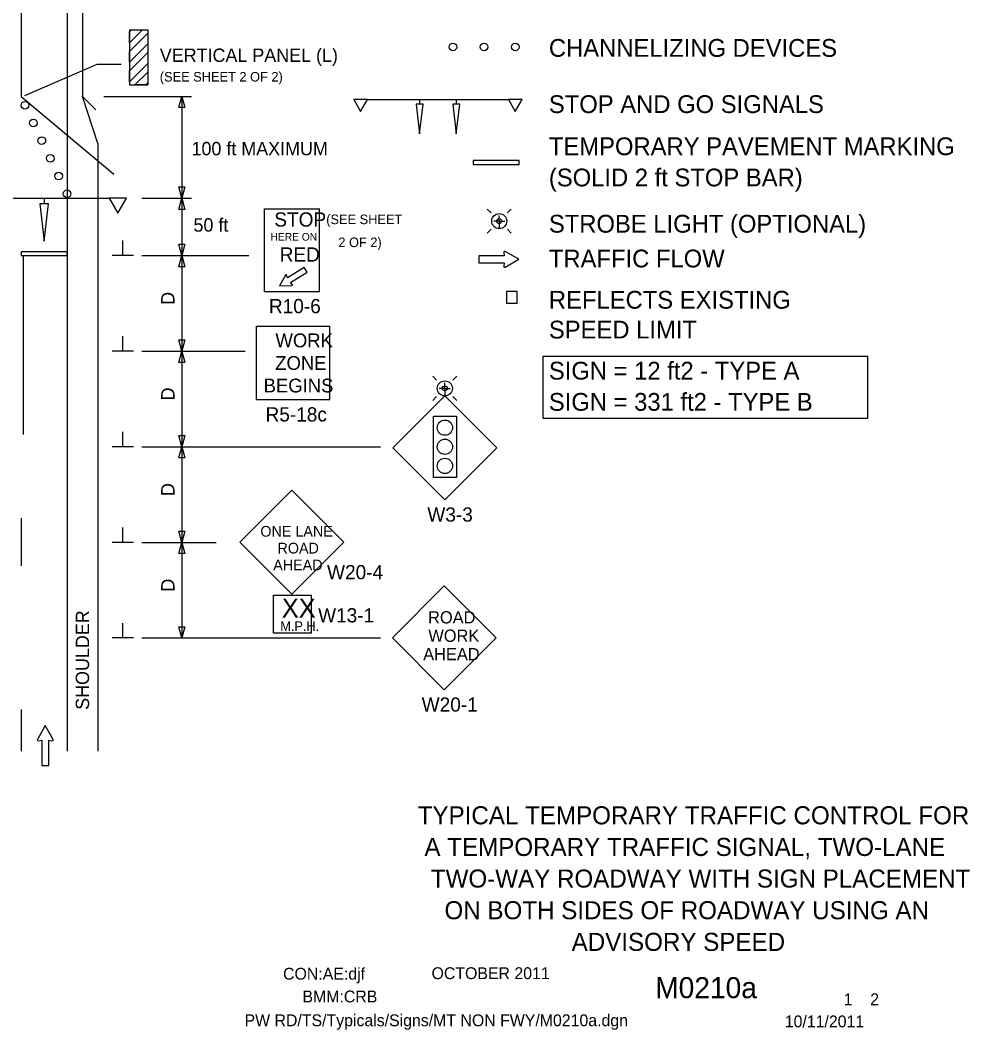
# Model space of a CAD drawing. Extents: x 16520 to 18479, y 5662 to 6927.
# Drawn here: x 16953 to 17450, y 5932 to 6460 of the extents above; entities that cross this region are included whole.
import ezdxf

# ---------------------------------------------------------------- set-up
doc = ezdxf.new("R2010")
doc.units = 0
for name, color, linetype in [('ALI_LEGAL_EX', 7, 'Continuous'), ('BORDER', 7, 'Continuous'), ('BORDER_SIGNAL_WO', 7, 'Continuous'), ('MT_SCRATCH_LEVEL_E', 7, 'Continuous'), ('PAVT_EDGE_EX', 7, 'Continuous'), ('TRAFFIC_SIGNS_PR', 7, 'Continuous'), ('TYPICAL_TEXT_DIMEN_EX', 7, 'Continuous'), ('TYPICAL_TEXT_DIMEN_PR', 7, 'Continuous')]:
    doc.layers.add(name, color=color, linetype=linetype)

msp = doc.modelspace()

# ---------------------------------------------------------------- linework, layer by layer
at = {"layer": 'ALI_LEGAL_EX'}
for points in [[(16954.78, 6336.76), (16954.78, 6243.13)], [(16953.78, 6199.43), (16953.78, 6174.43)], [(16953.78, 6099.43), (16953.78, 6077.5)]]:
    msp.add_lwpolyline(points, dxfattribs=at)
at = {"layer": 'MT_SCRATCH_LEVEL_E'}
for p, q in [((17206.32, 6336.64), (17193.07, 6336.64)), ((17193.07, 6336.64), (17193.07, 6332.9)), ((17206.32, 6336.64), (17193.07, 6336.64)), ((17193.07, 6336.64), (17193.07, 6332.9)), ((17206.01, 6338.42), (17206.32, 6336.64)), ((17206.01, 6338.42), (17206.32, 6336.64)), ((17213.93, 6334.79), (17206.69, 6338.9)), ((17213.93, 6334.79), (17206.69, 6338.9)), ((17193.07, 6332.9), (17206.32, 6332.9)), ((17193.07, 6332.9), (17206.32, 6332.9)), ((17206.32, 6332.9), (17206.01, 6331.12)), ((17206.32, 6332.9), (17206.01, 6331.12)), ((17206.69, 6330.64), (17213.93, 6334.79)), ((17206.69, 6330.64), (17213.93, 6334.79)), ((16966.37, 6090.97), (16962.26, 6083.73)), ((16966.37, 6090.97), (16962.26, 6083.73)), ((16970.52, 6083.73), (16966.37, 6090.97)), ((16970.52, 6083.73), (16966.37, 6090.97)), ((16962.74, 6083.04), (16964.52, 6083.36)), ((16962.74, 6083.04), (16964.52, 6083.36)), ((16964.52, 6083.36), (16964.52, 6070.1)), ((16964.52, 6083.36), (16964.52, 6070.1)), ((16968.26, 6070.1), (16968.26, 6083.36)), ((16968.26, 6083.36), (16970.04, 6083.04)), ((16968.26, 6070.1), (16968.26, 6083.36)), ((16968.26, 6083.36), (16970.04, 6083.04)), ((16964.52, 6070.1), (16968.26, 6070.1)), ((16964.52, 6070.1), (16968.26, 6070.1))]:
    msp.add_line(p, q, dxfattribs=at)
for centre, start, end in [((17206.47, 6338.49), 60.4248, 189.9638), ((17206.47, 6338.49), 60.4248, 189.9638), ((17206.47, 6331.05), 170.0362, 299.7731), ((17206.47, 6331.05), 170.0362, 299.7731), ((16962.67, 6083.5), 150.4248, 279.9638), ((16962.67, 6083.5), 150.4248, 279.9638), ((16970.11, 6083.5), 260.0362, 29.7731), ((16970.11, 6083.5), 260.0362, 29.7731)]:
    msp.add_arc(centre, 0.463, start, end, dxfattribs=at)
at = {"layer": 'PAVT_EDGE_EX'}
for p, q in [((16977.78, 6899.43), (16977.78, 6077.5)), ((16953.78, 6551.35), (16953.78, 6419.96)), ((16985.78, 6551.35), (16985.78, 6419.96)), ((16953.78, 6419.96), (17002.19, 6379.34)), ((16985.78, 6419.96), (16992.85, 6412.89)), ((16993.78, 6395.26), (16985.78, 6419.96)), ((16993.78, 6395.26), (16993.78, 6077.5))]:
    msp.add_line(p, q, dxfattribs=at)
at = {"layer": 'TRAFFIC_SIGNS_PR'}
for p, q in [((17010.4, 6454.77), (17020, 6454.77)), ((17010.4, 6454.77), (17010.4, 6425.97)), ((17010.4, 6453.68), (17011.49, 6454.77)), ((17010.4, 6448.02), (17017.15, 6454.77)), ((17010.4, 6454.77), (17020, 6454.77)), ((17010.4, 6454.77), (17010.4, 6425.97)), ((17010.4, 6453.68), (17011.49, 6454.77)), ((17010.4, 6448.02), (17017.15, 6454.77)), ((17010.4, 6443.5), (17020, 6453.1)), ((17010.4, 6443.5), (17020, 6453.1)), ((17020, 6454.77), (17020, 6425.97)), ((17020, 6454.77), (17020, 6425.97)), ((17010.4, 6437.84), (17020, 6447.44)), ((17010.4, 6437.84), (17020, 6447.44)), ((17010.4, 6433.32), (17020, 6442.92)), ((17010.4, 6433.32), (17020, 6442.92)), ((17011.81, 6444.91), (17013.23, 6446.33)), ((17011.81, 6444.91), (17013.23, 6446.33)), ((17010.4, 6427.66), (17020, 6437.26)), ((17010.4, 6427.66), (17020, 6437.26)), ((17013.24, 6425.97), (17020, 6432.73)), ((17013.24, 6425.97), (17020, 6432.73)), ((17010.4, 6425.97), (17020, 6425.97)), ((17010.4, 6425.97), (17020, 6425.97)), ((17018.89, 6425.97), (17020, 6427.08)), ((17018.89, 6425.97), (17020, 6427.08)), ((17134.84, 6418.4), (17208.44, 6418.4)), ((17162.04, 6418.4), (17162.04, 6415.98)), ((17181.24, 6418.4), (17181.24, 6415.98)), ((16907.78, 6366.76), (16999.78, 6366.76)), ((16965.78, 6366.76), (16965.78, 6363.74)), ((17080.91, 6361.23), (17109.71, 6361.23)), ((17080.91, 6318.03), (17080.91, 6361.23)), ((17095.31, 6361.23), (17095.31, 6361.23)), ((17109.71, 6318.03), (17109.71, 6361.23)), ((17199.4, 6359.04), (17197.37, 6361.07)), ((17203.68, 6354.76), (17203.68, 6357.63)), ((17207.96, 6359.04), (17209.99, 6361.07)), ((17203.68, 6354.76), (17200.8, 6354.76)), ((17203.68, 6354.76), (17203.68, 6350.82)), ((17203.68, 6354.76), (17206.56, 6354.76)), ((17199.4, 6350.47), (17197.37, 6348.44)), ((17209.99, 6348.44), (17207.96, 6350.47)), ((17080.91, 6318.03), (17109.71, 6318.03)), ((17076.71, 6261.4), (17076.71, 6299.8)), ((17076.71, 6299.8), (17115.11, 6299.8)), ((17115.11, 6261.4), (17115.11, 6299.8)), ((17170.94, 6271.56), (17168.91, 6273.59)), ((17179.5, 6271.56), (17181.53, 6273.59)), ((17175.22, 6267.28), (17172.34, 6267.28)), ((17175.22, 6267.28), (17175.22, 6270.16)), ((17175.22, 6267.28), (17175.22, 6263.34)), ((17175.22, 6267.28), (17178.1, 6267.28)), ((17175.22, 6263.34), (17148.07, 6236.19)), ((17170.94, 6263), (17168.91, 6260.96)), ((17202.37, 6236.19), (17175.22, 6263.34)), ((17181.53, 6260.96), (17179.5, 6263)), ((17076.71, 6261.4), (17115.11, 6261.4)), ((17148.07, 6236.19), (17175.22, 6209.03)), ((17175.22, 6209.03), (17202.37, 6236.19)), ((17095.23, 6214.01), (17068.08, 6186.86)), ((17122.39, 6186.86), (17095.23, 6214.01)), ((17068.08, 6186.86), (17095.23, 6159.71)), ((17095.23, 6159.71), (17122.39, 6186.86)), ((17174.97, 6163.96), (17147.82, 6136.81)), ((17202.12, 6136.81), (17174.97, 6163.96)), ((17085.63, 6159.2), (17105.48, 6159.2)), ((17085.63, 6139.36), (17085.63, 6159.2)), ((17105.48, 6139.36), (17105.48, 6159.2)), ((17085.63, 6139.36), (17105.48, 6139.36)), ((17147.82, 6136.81), (17174.97, 6109.66)), ((17174.97, 6109.66), (17202.12, 6136.81))]:
    msp.add_line(p, q, dxfattribs=at)
for points in [[(17011.49, 6454.77), (17017.15, 6454.77), (17010.4, 6448.02), (17010.4, 6453.68)], [(17011.49, 6454.77), (17017.15, 6454.77), (17010.4, 6448.02), (17010.4, 6453.68)], [(17010.4, 6443.5), (17020, 6453.1), (17020, 6447.44), (17010.4, 6437.84)], [(17010.4, 6443.5), (17020, 6453.1), (17020, 6447.44), (17010.4, 6437.84)], [(17010.4, 6433.32), (17020, 6442.92), (17020, 6437.26), (17010.4, 6427.66)], [(17010.4, 6433.32), (17020, 6442.92), (17020, 6437.26), (17010.4, 6427.66)], [(17020, 6432.73), (17020, 6427.08), (17018.89, 6425.97), (17013.24, 6425.97)], [(17020, 6432.73), (17020, 6427.08), (17018.89, 6425.97), (17013.24, 6425.97)], [(17127.64, 6418.4), (17131.24, 6412.16), (17134.84, 6418.4)], [(17160.24, 6415.98), (17162.04, 6400.44), (17163.84, 6415.98)], [(17179.44, 6415.98), (17181.24, 6400.44), (17183.04, 6415.98)], [(17208.44, 6418.4), (17212.04, 6412.16), (17215.64, 6418.4)], [(17190.06, 6386.37), (17190.06, 6384.37), (17214.06, 6384.37), (17214.06, 6386.37)], [(16963.53, 6363.74), (16965.78, 6344.32), (16968.03, 6363.74)], [(16999.78, 6366.76), (17004.28, 6358.97), (17008.78, 6366.76)], [(16953.78, 6338.76), (16953.78, 6336.76), (16977.78, 6336.76), (16977.78, 6338.76)], [(17207.46, 6311.82), (17213.05, 6311.82), (17213.05, 6317.99), (17207.46, 6317.99)], [(17181.28, 6220.73), (17169.28, 6220.73), (17169.28, 6252.73), (17181.28, 6252.73)]]:
    msp.add_lwpolyline(points, close=True, dxfattribs=at)
for points in [[(17091.92, 6326.48), (17088.87, 6320.84), (17095.26, 6321.09)], [(17095.51, 6321.68), (17094.59, 6322.71), (17103.24, 6328.07), (17101.73, 6330.51), (17093.07, 6325.16), (17092.56, 6326.44)]]:
    msp.add_lwpolyline(points, dxfattribs=at)
for centre, radius in [((17179.46, 6445.85), 2), ((17195.76, 6445.85), 2), ((17212.06, 6445.85), 2), ((16955.78, 6415.38), 2), ((16960.18, 6406.12), 2), ((16964.58, 6396.85), 2), ((16968.98, 6387.59), 2), ((16973.38, 6378.32), 2), ((16977.78, 6369.06), 2), ((17203.68, 6354.76), 3.94), ((17203.68, 6354.76), 1.28), ((17175.22, 6267.28), 3.94), ((17175.22, 6267.28), 1.28), ((17175.28, 6246.73), 4), ((17175.28, 6236.73), 4), ((17175.28, 6226.73), 4)]:
    msp.add_circle(centre, radius, dxfattribs=at)
for centre, radius, start, end in [((17092.23, 6326.31), 0.355, 21.7152, 151.4266), ((17095.25, 6321.44), 0.354, 272.1787, 41.9178)]:
    msp.add_arc(centre, radius, start, end, dxfattribs=at)
at = {"layer": 'TYPICAL_TEXT_DIMEN_EX'}
msp.add_lwpolyline([(17226.59, 6284.11), (17396.24, 6284.11), (17396.24, 6251.57), (17226.59, 6251.57)], close=True, dxfattribs=at)
at = {"layer": 'TYPICAL_TEXT_DIMEN_PR'}
for p, q in [((16955.78, 6420.47), (16993.57, 6436.91)), ((16955.78, 6420.47), (16993.57, 6436.91)), ((16993.57, 6436.91), (17006.03, 6436.91)), ((16993.57, 6436.91), (17006.03, 6436.91)), ((16997.08, 6419.96), (17042.78, 6419.96)), ((17036.21, 6414.1), (17037.78, 6419.96)), ((17037.78, 6419.96), (17037.78, 6366.76)), ((17037.78, 6419.96), (17039.35, 6414.1)), ((17037.78, 6414.1), (17036.21, 6414.1)), ((17039.35, 6414.1), (17037.78, 6414.1)), ((17037.78, 6366.76), (17036.21, 6372.63)), ((17036.21, 6372.63), (17037.78, 6372.63)), ((17037.78, 6372.63), (17039.35, 6372.63)), ((17039.35, 6372.63), (17037.78, 6366.76)), ((17016.78, 6366.76), (17042.78, 6366.76)), ((17036.21, 6360.9), (17037.78, 6366.76)), ((17037.78, 6366.76), (17039.35, 6360.9)), ((17037.78, 6366.76), (17037.78, 6336.76)), ((17037.78, 6360.9), (17036.21, 6360.9)), ((17039.35, 6360.9), (17037.78, 6360.9)), ((17006.91, 6336.76), (17006.91, 6344.55)), ((17037.78, 6336.76), (17036.21, 6342.63)), ((17036.21, 6342.63), (17037.78, 6342.63)), ((17037.78, 6342.63), (17039.35, 6342.63)), ((17039.35, 6342.63), (17037.78, 6336.76)), ((17012.53, 6336.76), (17001.28, 6336.76)), ((17016.78, 6336.76), (17072.75, 6336.76)), ((17036.21, 6330.9), (17037.78, 6336.76)), ((17037.78, 6336.76), (17037.78, 6286.76)), ((17037.78, 6336.76), (17039.35, 6330.9)), ((17037.78, 6330.9), (17036.21, 6330.9)), ((17039.35, 6330.9), (17037.78, 6330.9)), ((17006.91, 6286.76), (17006.91, 6294.55)), ((17037.78, 6286.76), (17036.21, 6292.63)), ((17036.21, 6292.63), (17037.78, 6292.63)), ((17037.78, 6292.63), (17039.35, 6292.63)), ((17039.35, 6292.63), (17037.78, 6286.76)), ((17012.53, 6286.76), (17001.28, 6286.76)), ((17016.78, 6286.76), (17070.8, 6286.76)), ((17036.21, 6280.9), (17037.78, 6286.76)), ((17036.21, 6280.9), (17037.78, 6286.76)), ((17037.78, 6286.76), (17037.78, 6236.76)), ((17037.78, 6286.76), (17039.35, 6280.9)), ((17037.78, 6286.76), (17039.35, 6280.9)), ((17037.78, 6280.9), (17036.21, 6280.9)), ((17037.78, 6280.9), (17036.21, 6280.9)), ((17039.35, 6280.9), (17037.78, 6280.9)), ((17039.35, 6280.9), (17037.78, 6280.9)), ((17006.91, 6236.76), (17006.91, 6244.55)), ((17037.78, 6236.76), (17036.21, 6242.63)), ((17036.21, 6242.63), (17037.78, 6242.63)), ((17037.78, 6236.76), (17036.21, 6242.63)), ((17036.21, 6242.63), (17037.78, 6242.63)), ((17037.78, 6242.63), (17039.35, 6242.63)), ((17039.35, 6242.63), (17037.78, 6236.76)), ((17037.78, 6242.63), (17039.35, 6242.63)), ((17039.35, 6242.63), (17037.78, 6236.76)), ((17012.53, 6236.76), (17001.28, 6236.76)), ((17016.78, 6236.76), (17141.66, 6236.76)), ((17036.21, 6230.9), (17037.78, 6236.76)), ((17036.21, 6230.9), (17037.78, 6236.76)), ((17037.78, 6236.76), (17037.78, 6186.76)), ((17037.78, 6236.76), (17039.35, 6230.9)), ((17037.78, 6236.76), (17039.35, 6230.9)), ((17037.78, 6230.9), (17036.21, 6230.9)), ((17037.78, 6230.9), (17036.21, 6230.9)), ((17039.35, 6230.9), (17037.78, 6230.9)), ((17039.35, 6230.9), (17037.78, 6230.9)), ((17006.91, 6186.76), (17006.91, 6194.55)), ((17037.78, 6186.76), (17036.21, 6192.63)), ((17036.21, 6192.63), (17037.78, 6192.63)), ((17037.78, 6192.63), (17039.35, 6192.63)), ((17039.35, 6192.63), (17037.78, 6186.76)), ((17012.53, 6186.76), (17001.28, 6186.76)), ((17016.78, 6186.76), (17055.78, 6186.76)), ((17036.21, 6180.9), (17037.78, 6186.76)), ((17037.78, 6186.76), (17037.78, 6136.76)), ((17037.78, 6186.76), (17039.35, 6180.9)), ((17037.78, 6180.9), (17036.21, 6180.9)), ((17039.35, 6180.9), (17037.78, 6180.9)), ((17006.91, 6136.76), (17006.91, 6144.55)), ((17037.78, 6136.76), (17036.21, 6142.63)), ((17036.21, 6142.63), (17037.78, 6142.63)), ((17037.78, 6142.63), (17039.35, 6142.63)), ((17039.35, 6142.63), (17037.78, 6136.76)), ((17012.53, 6136.76), (17001.28, 6136.76)), ((17016.78, 6136.76), (17141.66, 6136.76))]:
    msp.add_line(p, q, dxfattribs=at)

# ---------------------------------------------------------------- texts
at = {"layer": 'BORDER'}
for s, p in [('TYPICAL TEMPORARY TRAFFIC CONTROL FOR', (17161.04, 6039.31)), ('A TEMPORARY TRAFFIC SIGNAL, TWO-LANE', (17164.56, 6022.76)), ('TWO-WAY ROADWAY WITH SIGN PLACEMENT', (17167.92, 6006.22)), ('ON BOTH SIDES OF ROADWAY USING AN', (17175.04, 5989.66)), ('ADVISORY SPEED', (17241.52, 5973.11))]:
    msp.add_text(s, height=9.4427, dxfattribs=at).set_placement(p)
at = {"layer": 'BORDER_SIGNAL_WO'}
for s, height, p in [('CON:AE:djf', 6.2, (17090.69, 5958.06)), ('    OCTOBER 2011    ', 6.2, (17159.08, 5958.34)), ('    M0210a    ', 11, (17268.86, 5948.38)), ('BMM:CRB   ', 6.2, (17100.81, 5946.17)), (' 1    2 ', 6.2, (17381.45, 5944.7)), ('PW RD/TS/Typicals/Signs/MT NON FWY/M0210a.dgn     ', 6.2, (17070.55, 5933.71)), ('10/11/2011    ', 6.2, (17352.93, 5933.13))]:
    msp.add_text(s, height=height, dxfattribs=at).set_placement(p)
at = {"layer": 'TRAFFIC_SIGNS_PR'}
for s, height, p in [('STOP', 7.44, (17086.11, 6351.89)), ('HERE ON', 4, (17084.11, 6344.53)), ('RED', 7.44, (17088.92, 6333.58)), ('R10-6', 7.44, (17083.29, 6306.59)), ('WORK', 7.217, (17086.71, 6288.77)), ('ZONE', 7.217, (17086.59, 6276.95)), ('BEGINS', 7.217, (17080.52, 6265.15)), ('R5-18c', 7.44, (17081.52, 6249.96)), ('W3-3', 7.44, (17166.09, 6197.6)), ('ONE LANE', 5.6, (17078.82, 6189.73)), ('ROAD', 5.6, (17087.77, 6180.93)), ('AHEAD', 5.6, (17085.53, 6172.13)), ('W20-4', 7.44, (17113.67, 6167.44)), ('XX', 9.925, (17090.03, 6147.42)), ('W13-1', 7.44, (17109.01, 6144.9)), ('ROAD', 6.4, (17166.51, 6144.34)), ('M.P.H.', 4.961, (17089.25, 6140.46)), ('WORK', 6.4, (17166.62, 6134.74)), ('AHEAD', 6.4, (17163.93, 6125.14)), ('W20-1', 7.44, (17163.14, 6098.22))]:
    msp.add_text(s, height=height, dxfattribs=at).set_placement(p)
at = {"layer": 'TYPICAL_TEXT_DIMEN_EX'}
for s, p in [('CHANNELIZING DEVICES', (17229.62, 6440.68)), ('STOP AND GO SIGNALS', (17229.62, 6411.28)), ('TEMPORARY PAVEMENT MARKING', (17229.62, 6389.23)), ('(SOLID 2 ft STOP BAR)', (17229.62, 6372.93)), ('STROBE LIGHT (OPTIONAL)', (17229.62, 6348.73)), ('TRAFFIC FLOW', (17229.62, 6330.55)), ('REFLECTS EXISTING', (17229.62, 6308.97)), ('SPEED LIMIT', (17229.62, 6293.37)), ('SIGN = 12 ft2 - TYPE A', (17229.62, 6271.88)), ('SIGN = 331 ft2 - TYPE B', (17229.62, 6255.58))]:
    msp.add_text(s, height=9.3, dxfattribs=at).set_placement(p)
at = {"layer": 'TYPICAL_TEXT_DIMEN_PR'}
for s, height, p in [('VERTICAL PANEL (L)', 7, (17026.25, 6438)), ('VERTICAL PANEL (L)', 7, (17026.25, 6438)), ('(SEE SHEET 2 OF 2)', 5, (17026.25, 6427.75)), ('(SEE SHEET 2 OF 2)', 5, (17026.25, 6427.75)), ('100 ft MAXIMUM', 7, (17042.82, 6389.17)), ('(SEE SHEET', 5, (17113.25, 6353.17)), ('50 ft', 7, (17043.85, 6349.25)), ('2 OF 2)', 5, (17119.58, 6341.17))]:
    msp.add_text(s, height=height, dxfattribs=at).set_placement(p)
for s, p in [('D', (17033.94, 6310.98)), ('D', (17033.94, 6260.98)), ('D', (17033.94, 6260.98)), ('D', (17033.94, 6210.98)), ('D', (17033.94, 6160.98)), ('SHOULDER', (16989.31, 6099.18))]:
    msp.add_text(s, height=7, rotation=90, dxfattribs=at).set_placement(p)

doc.saveas('drawing.dxf')
